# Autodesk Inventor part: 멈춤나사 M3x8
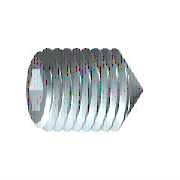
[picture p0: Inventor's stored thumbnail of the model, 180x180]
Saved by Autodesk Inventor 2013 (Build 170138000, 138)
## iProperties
IsCustomPart: 1
Created: 2012-02
Part Number: 멈춤나사 M3x8
Material: 강철, 연강
Description: 6각 소켓 머리 없는 멈춤 나사
Document SubType Name: Modeling
Standard: KS B 1028
Designer: test
Standards Organization: KS
Language: ko-KR
Size Designation: 원추점 M3x8
Categories: <MemberInstance><Categories><Category DisplayName="조임쇠" InternalName="e4da775c-781d-43d5-af7c-5136215cf5a6" Mnemonic="FSTN"><Category DisplayName="볼트" InternalN
Density: 1 g/cm^3
Author: test
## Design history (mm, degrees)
sketch "스케치1"
  geometry: L1 (0, 0)-(5.5, 0); L2 (8, 0.866)-(8, 1.5); L3 (8, 1.5)-(0, 1.5); L4 (8, 0.866)-(6, 0.866); L5 (6, 0.866)-(5.5, 0); L6 (0, -0.3)-(0, 1.8) reference; L7 (0, 1.5)-(0, 0)
  constraints: 13 end point, 3 parallel, 1 collinear, 1 perpendicular, 1 point on line
  dimensions: "d0" = 2 distance of L2.start L4.end (= INTI); "d1" = 60 deg angle of L5 L1; "d2" = 3 diameter of L3 L1 (= NND); "d3" = 1.73205 diameter of L4 L1 (= 1.1547 x SW); "d5" = 8 distance from line of L2 L3.end (= NLG)
revolve "본체" sketch "스케치1" stored, may be unused: angle "d6" = 90 deg
sketch "스케치2"
  geometry: L1 (-0.433, 0.75)-(0.433, 0.75); L2 (0.433, 0.75)-(0.866, 0); L3 (0.866, 0)-(0.433, -0.75); L4 (0.433, -0.75)-(-0.433, -0.75); L5 (-0.433, -0.75)-(-0.866, 0); L6 (-0.866, 0)-(-0.433, 0.75); 3 further points
  constraints: 12 end point, 1 coincident, 1 horizontal, 13 other
extrude "슬롯" join sketch "스케치2" taper "d7" = 0 deg; stored distance "d21" = 10
workaxis "Work Axis1"
workplane "Work Plane1"
sketch "스케치4"
  geometry: L1 (0, 0.15)-(-1.35, 1.5) reference; L2 (0, -0.15)-(-1.35, -1.5) reference; L3 (-1.35, -1.5)-(0.15, 0); L4 (-1.35, 1.5)-(0.15, 0); 2 further points
  constraints: 4 end point, 1 coincident, 1 collinear, 1 horizontal alignment
node "작업점1"
body "Solid1"
feature "스레드" dims "d12" = 8 (= NLG), "d13" = 0
chamfer "모따기1" distance "d8" = 1.35 (computed from NND, SPD, FAWI); stored, may be unused: angle "d9" = 45 deg (= FAWI), second distance "d34" = 1.35 (computed from NND, SPD, FAWI)
chamfer "모따기2" distance "d10" = 0.30673 (= -0.5 x GD1 + 0.5 x NND); stored, may be unused: angle "d11" = 45 deg (= FAWI), second distance "d35" = 0.30673 (= -0.5 x GD1 + 0.5 x NND)
other parameters: "NND" = 3 [user parameter; used in 5 equation terms], "NLG" = 8 [user parameter; used in 2 equation terms], "INTI" = 2 [user parameter; used in 1 equation term], "FAWI" = 45 deg [user parameter; used in 4 equation terms], "SW" = 1.5 [user parameter; used in 2 equation terms], "GD1" = 2.38655 (= THREADDIA - 1.2269 x PTC) [user parameter; used in 2 equation terms], "d4" = 0, "FAWI1" = 45 deg [user parameter], "SPD" = 0.3 [user parameter; used in 2 equation terms], "d36" = 0, "d37" = 0, "GUL" = 0.30673 (= 0.61345 x PTC) [user parameter], "TOA" = 30 deg [user parameter], "THREADDIA" = 3 [user parameter; used in 1 equation term], "PTC" = 0.5 [user parameter; used in 4 equation terms], "GAL" = 0.30673 (= 0.61345 x PTC) [user parameter], "E0" = 1.7325 (= 1.155 x SW) [user parameter]
